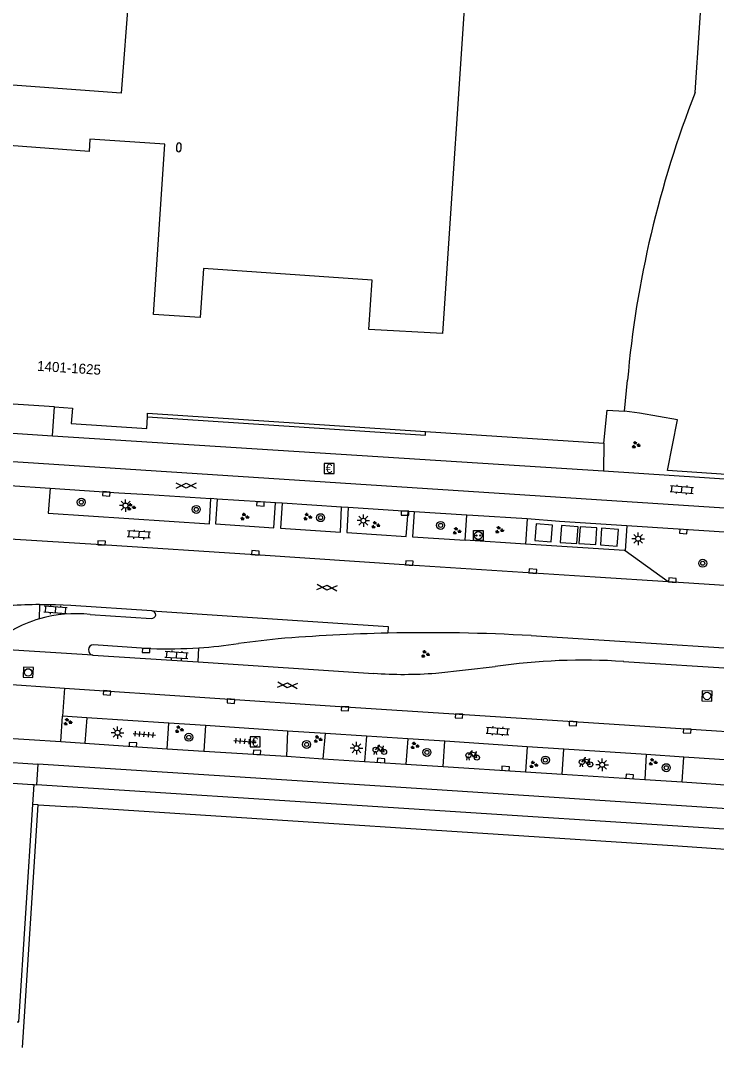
# Model space of a CAD drawing. Extents: x 132998 to 136004, y 396998 to 398512.
# Drawn here: x 133600.6 to 133670.3, y 397000 to 397102.8 of the extents above; entities that cross this region are included whole.
import ezdxf

# ---------------------------------------------------------------- set-up
doc = ezdxf.new("R2010")
doc.units = 0
for name, color, linetype in [('gg-afsc-hekwerk', 7, 'Continuous'), ('gg-anno-huisnummerreeks BGT', 7, 'Continuous'), ('gg-bbg-hoofdgebouw', 7, 'Continuous'), ('gg-bbg-onder overbouw', 7, 'Continuous'), ('gg-bbg-pand overbouw', 7, 'Continuous'), ('gg-knt-verharding', 7, 'Continuous'), ('gg-knt-verharding nz', 7, 'Continuous'), ('gg-kwrk-afval apart plaats', 7, 'Continuous'), ('gt-grn-vlakafsluiter', 7, 'Continuous'), ('gt-grn-weggrens', 7, 'Continuous'), ('gt-symb-betaalautomaat', 7, 'Continuous'), ('gt-symb-boom', 7, 'Continuous'), ('gt-symb-brandkraan', 7, 'Continuous'), ('gt-symb-fietsenrek', 7, 'Continuous'), ('gt-symb-gesloten verharding', 7, 'Continuous'), ('gt-symb-groenvak', 7, 'Continuous'), ('gt-symb-klinker verharding', 7, 'Continuous'), ('gt-symb-kolk', 7, 'Continuous'), ('gt-symb-laadpunt elektrisch vervoer', 7, 'Continuous'), ('gt-symb-lichtmast', 7, 'Continuous'), ('gt-symb-rioolschacht', 7, 'Continuous'), ('gt-symb-tegel verharding', 7, 'Continuous')]:
    doc.layers.add(name, color=color, linetype=linetype)

# ---------------------------------------------------------------- blocks, each defined once
blk = doc.blocks.new('gt0-BR')
at = {"layer": 'gt-symb-brandkraan'}
for centre, radius, start, end in [((-0.24, 0), 0.206, 107.5669, 252.4331), ((0.6, -2.66), 3, 106.892, 107.5669), ((0, -0.69), 0.938, 73.108, 106.892), ((-0.6, -2.66), 3, 72.4331, 73.108), ((0.24, 0), 0.206, 287.567, 72.4331), ((0.6, 2.66), 3, 252.4331, 253.108), ((0, 0.69), 0.938, 253.108, 286.8921), ((-0.6, 2.66), 3, 286.8921, 287.567)]:
    blk.add_arc(centre, radius, start, end, dxfattribs=at)
blk = doc.blocks.new('gt0-KOLK')
at = {"layer": 'gt-symb-kolk'}
blk.add_lwpolyline([(0, 0), (0.38, 0), (0.38, 0.4), (-0.37, 0.4), (-0.37, 0), (0, 0)], dxfattribs=at)
blk = doc.blocks.new('gt0-TEG1')
at = {"layer": 'gt-symb-tegel verharding'}
for p, q in [((-1.12, 0), (1.13, 0)), ((-0.9, -0.25), (-0.9, 0.25)), ((-0.45, -0.25), (-0.45, 0.25)), ((0, -0.25), (0, 0.25)), ((0.45, -0.25), (0.45, 0.25)), ((0.9, -0.25), (0.9, 0.25))]:
    blk.add_line(p, q, dxfattribs=at)
blk = doc.blocks.new('gt0-KL1')
at = {"layer": 'gt-symb-klinker verharding'}
for p, q in [((-1.15, 0.3), (1.15, 0.3)), ((-1, -0.3), (-1, 0.3)), ((-0.5, 0.3), (-0.5, 0.45)), ((0, -0.3), (0, 0.3)), ((0.5, 0.3), (0.5, 0.45)), ((1, -0.3), (1, 0.3)), ((-1.15, -0.3), (1.15, -0.3)), ((-0.5, -0.45), (-0.5, -0.3)), ((0.5, -0.45), (0.5, -0.3))]:
    blk.add_line(p, q, dxfattribs=at)
blk = doc.blocks.new('gt0-GRVAK')
at = {"layer": 'gt-symb-groenvak'}
for p, q in [((-0.11, 0.19), (-0.23, 0.24)), ((-0.18, 0.15), (0.09, 0.15)), ((-0.09, 0.21), (-0.16, 0.32)), ((-0.05, 0.21), (-0.05, 0.39)), ((0, 0.21), (0.06, 0.32)), ((0.02, 0.19), (0.13, 0.24)), ((0.26, -0.05), (0.2, 0.06)), ((0.31, -0.05), (0.31, 0.13)), ((0.35, -0.05), (0.41, 0.06)), ((-0.24, -0.23), (-0.36, -0.18)), ((-0.32, -0.26), (-0.05, -0.26)), ((-0.23, -0.21), (-0.29, -0.09)), ((-0.18, -0.2), (-0.18, -0.02)), ((-0.14, -0.21), (-0.07, -0.09)), ((-0.12, -0.23), (0, -0.18)), ((0.24, -0.07), (0.12, -0.02)), ((0.17, -0.11), (0.44, -0.11)), ((0.37, -0.07), (0.49, -0.02))]:
    blk.add_line(p, q, dxfattribs=at)
blk = doc.blocks.new('gt0-LMAST')
at = {"layer": 'gt-symb-lichtmast'}
for p, q in [((-0.18, 0.17), (-0.45, 0.44)), ((-0.01, 0.25), (-0.01, 0.62)), ((0.17, 0.17), (0.44, 0.44)), ((-0.26, 0), (-0.63, 0)), ((-0.18, -0.18), (-0.45, -0.45)), ((-0.01, -0.25), (-0.01, -0.63)), ((0.44, -0.45), (0.17, -0.18)), ((0.24, 0), (0.62, 0))]:
    blk.add_line(p, q, dxfattribs=at)
blk.add_circle((-0.01, 0), 0.25, dxfattribs=at)
blk = doc.blocks.new('gt0-RS')
at = {"layer": 'gt-symb-rioolschacht'}
blk.add_lwpolyline([(-0.5, -0.5), (0.5, -0.5), (0.5, 0.5), (-0.5, 0.5)], close=True, dxfattribs=at)
blk.add_circle((0, 0), 0.375, dxfattribs=at)
blk = doc.blocks.new('gt0-BOOM')
at = {"layer": 'gt-symb-boom'}
for radius in [0.4, 0.2]:
    blk.add_circle((0, 0), radius, dxfattribs=at)
blk = doc.blocks.new('gt0-FREK')
at = {"layer": 'gt-symb-fietsenrek'}
for p, q in [((0.26, 0.76), (0.29, 0.82)), ((0.54, 0.34), (0.26, 0.76)), ((0.29, 0.82), (0.77, 0.71)), ((0.77, 0.71), (0.54, 0.34)), ((0.76, 0.84), (0.87, 0.82)), ((0.77, 0.71), (0.84, 0.82)), ((0.89, 0.25), (0.77, 0.71))]:
    blk.add_line(p, q, dxfattribs=at)
for points in [[(-0.12, 0), (-0.05, 0.31), (0.05, 0.31), (0.12, 0)], [(0.04, 0.48), (0.23, 0.71), (0.26, 0.76)], [(0.29, 0.82), (0.36, 0.94), (0.45, 0.93)], [(0.54, 0.34), (0.56, 0.31), (0.89, 0.25)]]:
    blk.add_lwpolyline(points, dxfattribs=at)
for centre in [(0.04, 0.48), (0.89, 0.25)]:
    blk.add_circle(centre, 0.252, dxfattribs=at)
blk = doc.blocks.new('gt0-GESVH1')
at = {"layer": 'gt-symb-gesloten verharding'}
for p, q in [((-0.99, -0.26), (0.01, 0.24)), ((0.01, -0.26), (-0.99, 0.24)), ((0.01, 0.24), (1.01, -0.26)), ((1.01, 0.24), (0.01, -0.26))]:
    blk.add_line(p, q, dxfattribs=at)
blk = doc.blocks.new('gt0-LEV')
at = {"layer": 'gt-symb-laadpunt elektrisch vervoer'}
blk.add_lwpolyline([(-0.49, 0.5), (0.49, 0.5), (0.49, -0.5), (-0.49, -0.5)], close=True, dxfattribs=at)
for centre, radius in [((0, 0), 0.393), ((-0.19, 0), 0.0566), ((0.19, 0), 0.0566)]:
    blk.add_circle(centre, radius, dxfattribs=at)
blk = doc.blocks.new('gt0-BA')
at = {"layer": 'gt-symb-betaalautomaat'}
blk.add_lwpolyline([(-0.5, -0.51), (0.5, -0.51), (0.5, 0.49), (-0.5, 0.49)], close=True, dxfattribs=at)
blk.add_text('€', height=0.9, dxfattribs=at).set_placement((-0.36, -0.46))

msp = doc.modelspace()

# ---------------------------------------------------------------- linework, layer by layer
at = {"layer": 'gg-afsc-hekwerk'}
for p, q in [((133600.79, 397000), (133602.36, 397024.29)), ((133600.79, 397000), (133602.36, 397024.29)), ((133602.36, 397024.29), (133605.79, 397024.07)), ((133602.36, 397024.29), (133605.79, 397024.07)), ((133666.45, 397020.13), (133605.79, 397024.07)), ((133666.45, 397020.13), (133605.79, 397024.07)), ((133690.95, 397018.53), (133666.45, 397020.13)), ((133690.95, 397018.53), (133666.45, 397020.13))]:
    msp.add_line(p, q, dxfattribs=at)
msp.add_lwpolyline([(133694.45, 397060.84), (133694.48, 397060.57), (133697.15, 397060.84), (133696.74, 397055.62), (133665.4, 397057.74), (133666.4, 397062.8), (133662.61, 397063.49), (133661.11, 397063.68)], dxfattribs=at)
at = {"layer": 'gg-bbg-hoofdgebouw'}
for p, q in [((133661.11, 397063.68), (133661.39, 397066.77)), ((133641.16, 397061.65), (133659.03, 397060.48))]:
    msp.add_line(p, q, dxfattribs=at)
for points in [[(133614.52, 397145.58), (133610.67, 397095.5), (133598.44, 397096.41)], [(133668.18, 397095.57), (133669.05, 397108.54), (133645.45, 397109.99), (133642.88, 397071.45), (133635.49, 397071.85), (133635.82, 397076.8), (133618.93, 397077.94), (133618.6, 397073.05), (133613.91, 397073.35), (133615.04, 397090.41), (133607.55, 397090.9), (133607.47, 397089.68), (133598.11, 397090.36), (133597.34, 397078.54), (133592.67, 397078.86), (133592.72, 397079.67), (133565.07, 397081.52), (133564.74, 397076.63), (133560.06, 397076.94), (133561.47, 397098.82), (133552.17, 397099.42)], [(133604, 397064.1), (133605.8, 397063.98), (133605.69, 397062.45), (133613.24, 397061.93), (133613.31, 397063.1)], [(133659.03, 397060.48), (133659.36, 397063.77), (133661.11, 397063.68)]]:
    msp.add_lwpolyline(points, dxfattribs=at)
msp.add_arc((133764.66, 397057.62), 103.67, 158.529, 174.9372, dxfattribs=at)
at = {"layer": 'gg-bbg-onder overbouw'}
msp.add_line((133604, 397064.1), (133547.4, 397067.79), dxfattribs=at)
msp.add_lwpolyline([(133613.31, 397063.1), (133613.33, 397063.48), (133641.16, 397061.65)], dxfattribs=at)
at = {"layer": 'gg-bbg-pand overbouw'}
for p, q in [((133603.79, 397061.22), (133604, 397064.1)), ((133596.29, 397061.71), (133603.79, 397061.22))]:
    msp.add_line(p, q, dxfattribs=at)
msp.add_lwpolyline([(133613.31, 397063.1), (133641.15, 397061.28), (133641.16, 397061.65)], dxfattribs=at)
at = {"layer": 'gg-knt-verharding'}
for p, q in [((133696.47, 397052.34), (133548.81, 397061.91)), ((133659.03, 397060.48), (133658.98, 397057.7)), ((133658.98, 397057.7), (133697.52, 397055.19)), ((133599.54, 397056.24), (133603.57, 397055.97)), ((133620.29, 397054.88), (133619.66, 397054.93)), ((133626.8, 397054.48), (133626.13, 397054.52)), ((133632.76, 397054.08), (133626.8, 397054.48)), ((133633.42, 397054.04), (133632.76, 397054.08)), ((133639.44, 397053.65), (133633.42, 397054.04)), ((133640.04, 397053.6), (133639.44, 397053.65)), ((133645.32, 397053.27), (133640.04, 397053.6)), ((133645.13, 397050.76), (133645.32, 397053.27)), ((133645.91, 397053.24), (133645.32, 397053.27)), ((133651.35, 397052.89), (133645.91, 397053.24)), ((133651.35, 397052.89), (133651.19, 397050.38)), ((133661.32, 397052.21), (133661.15, 397049.7)), ((133692.12, 397050.22), (133661.32, 397052.21)), ((133651.19, 397050.38), (133645.13, 397050.76)), ((133665.46, 397046.6), (133661.15, 397049.7)), ((133665.46, 397046.6), (133658.15, 397047.07)), ((133602.5, 397042.9), (133602.52, 397044.31)), ((133607.57, 397043.33), (133613.69, 397042.93)), ((133690.52, 397038.72), (133651.75, 397041.21)), ((133618.38, 397038.59), (133618.47, 397039.99)), ((133626.41, 397040.89), (133622.43, 397040.43)), ((133607.84, 397039.27), (133618.38, 397038.59)), ((133618.38, 397038.59), (133635.96, 397037.44)), ((133642.2, 397037.46), (133648.13, 397038.11)), ((133661.01, 397038.63), (133690.67, 397036.75)), ((133593.19, 397036.74), (133605, 397035.97)), ((133604.64, 397030.62), (133604.82, 397033.15)), ((133607.23, 397032.99), (133604.82, 397033.15)), ((133607.23, 397032.99), (133607.04, 397030.45)), ((133615.46, 397032.45), (133607.23, 397032.99)), ((133615.29, 397029.89), (133615.46, 397032.45)), ((133619.13, 397032.21), (133615.46, 397032.45)), ((133619.13, 397032.21), (133618.97, 397029.66)), ((133627.33, 397031.67), (133619.13, 397032.21)), ((133554.05, 397031.49), (133602.32, 397028.36)), ((133592.9, 397031.37), (133604.64, 397030.62)), ((133627.33, 397031.67), (133627.23, 397029.14)), ((133631.15, 397031.42), (133627.33, 397031.67)), ((133630.93, 397028.9), (133631.15, 397031.42)), ((133635.26, 397031.15), (133631.15, 397031.42)), ((133639.38, 397030.88), (133635.26, 397031.15)), ((133639.38, 397030.88), (133639.19, 397028.36)), ((133643.09, 397030.64), (133639.38, 397030.88)), ((133604.64, 397030.62), (133607.04, 397030.45)), ((133615.29, 397029.89), (133618.97, 397029.66)), ((133618.97, 397029.66), (133627.23, 397029.14)), ((133642.94, 397028.12), (133643.09, 397030.64)), ((133651.34, 397030.09), (133643.09, 397030.64)), ((133651.34, 397030.09), (133651.19, 397027.59)), ((133655.01, 397029.85), (133651.34, 397030.09)), ((133654.86, 397027.35), (133655.01, 397029.85)), ((133663.27, 397029.31), (133655.01, 397029.85)), ((133627.23, 397029.14), (133630.93, 397028.9)), ((133630.93, 397028.9), (133635.06, 397028.63)), ((133635.06, 397028.63), (133639.19, 397028.36)), ((133663.27, 397029.31), (133663.12, 397026.82)), ((133667.03, 397029.06), (133663.27, 397029.31)), ((133666.87, 397026.57), (133667.03, 397029.06)), ((133675.43, 397028.51), (133667.03, 397029.06)), ((133602.32, 397028.36), (133602.19, 397026.29)), ((133639.19, 397028.36), (133642.94, 397028.12)), ((133642.94, 397028.12), (133651.19, 397027.59)), ((133651.19, 397027.59), (133654.86, 397027.35)), ((133654.86, 397027.35), (133663.12, 397026.82)), ((133663.12, 397026.82), (133666.87, 397026.57)), ((133666.87, 397026.57), (133675.26, 397026.02)), ((133601.84, 397024.32), (133601.97, 397026.3)), ((133601.97, 397026.3), (133602.19, 397026.29)), ((133691.05, 397020.56), (133602.19, 397026.29))]:
    msp.add_line(p, q, dxfattribs=at)
for points in [[(133603.57, 397055.97), (133603.38, 397053.46), (133619.52, 397052.4), (133619.66, 397054.93)], [(133603.57, 397055.97), (133610.44, 397055.52), (133613.45, 397055.34), (133619.66, 397054.93)], [(133620.29, 397054.88), (133620.14, 397052.39), (133625.97, 397052.01), (133626.13, 397054.52)], [(133626.13, 397054.52), (133624.65, 397054.6), (133620.29, 397054.88)], [(133626.8, 397054.48), (133626.65, 397051.96), (133632.64, 397051.56), (133632.76, 397054.08)], [(133658.15, 397047.07), (133639.53, 397048.28), (133624.11, 397049.3), (133608.7, 397050.29), (133596.26, 397051.07), (133565.43, 397053.1), (133552.27, 397053.95)], [(133633.42, 397054.04), (133633.29, 397051.52), (133639.24, 397051.12), (133639.44, 397053.65)], [(133640.04, 397053.6), (133639.86, 397051.1), (133645.13, 397050.76)], [(133661.32, 397052.21), (133654.57, 397052.65), (133651.35, 397052.89)], [(133661.15, 397049.7), (133661.1, 397049.73), (133651.19, 397050.38)], [(133688.59, 397045.11), (133678.33, 397045.76), (133665.46, 397046.6)], [(133613.75, 397043.7), (133605.64, 397044.22), (133604.09, 397044.29), (133602.52, 397044.31)], [(133613.66, 397039.91), (133613.19, 397039.92), (133607.9, 397040.3)], [(133605, 397035.97), (133633.12, 397034.1), (133644.54, 397033.37), (133655.95, 397032.61), (133685.71, 397030.67)], [(133607.04, 397030.45), (133611.84, 397030.11), (133615.29, 397029.89)], [(133685.16, 397022.97), (133641.29, 397025.85), (133602.32, 397028.36)], [(133600.25, 397002.56), (133600.43, 397002.55), (133601.84, 397024.32)]]:
    msp.add_lwpolyline(points, dxfattribs=at)
for centre, radius, start, end in [((133602.64, 396998.37), 45.95, 90.152, 97.605), ((133606.09, 397030.57), 12.84, 83.3634, 106.2181), ((133613.7, 397043.39), 0.46, 269.1351, 344.8887), ((133613.7, 397043.26), 0.444, 1.9655, 82.823), ((133606.09, 397030.57), 12.84, 106.2367, 132.5705), ((133641.37, 396861.04), 180.47, 91.2603, 94.7571), ((133641.39, 396860.82), 180.69, 86.7142, 91.2651), ((133607.93, 397039.78), 0.521, 93.788, 259.5636), ((133615.3, 397085.84), 45.95, 267.9534, 273.9528), ((133615.33, 397085.88), 46, 273.9083, 278.8769), ((133656.97, 396978.15), 60.61, 86.174, 98.3862), ((133638.97, 397079.01), 41.67, 265.8527, 274.4411)]:
    msp.add_arc(centre, radius, start, end, dxfattribs=at)
at = {"layer": 'gg-knt-verharding nz'}
for p, q in [((133607.84, 397039.27), (133597.07, 397039.92)), ((133605, 397035.97), (133604.82, 397033.15)), ((133635.26, 397031.15), (133635.06, 397028.63)), ((133601.8, 397026.31), (133601.97, 397026.3))]:
    msp.add_line(p, q, dxfattribs=at)
for points in [[(133613.75, 397043.7), (133637.42, 397042.14), (133637.4, 397041.46)], [(133593.87, 397022.76), (133594.18, 397026.8), (133601.8, 397026.31)]]:
    msp.add_lwpolyline(points, dxfattribs=at)
at = {"layer": 'gg-kwrk-afval apart plaats'}
for points in [[(133653.75, 397050.61), (133653.88, 397052.28), (133652.24, 397052.39), (133652.13, 397050.72), (133653.75, 397050.61)], [(133656.33, 397050.45), (133656.45, 397052.11), (133654.79, 397052.22), (133654.66, 397050.55), (133656.33, 397050.45)], [(133658.21, 397050.33), (133658.33, 397051.99), (133656.66, 397052.1), (133656.53, 397050.43), (133658.21, 397050.33)], [(133660.36, 397050.18), (133660.48, 397051.85), (133658.8, 397051.96), (133658.68, 397050.29), (133660.36, 397050.18)]]:
    msp.add_lwpolyline(points, dxfattribs=at)
at = {"layer": 'gt-grn-vlakafsluiter'}
msp.add_line((133602.36, 397024.29), (133601.84, 397024.32), dxfattribs=at)
at = {"layer": 'gt-grn-weggrens'}
msp.add_line((133603.79, 397061.22), (133658.98, 397057.7), dxfattribs=at)

# ---------------------------------------------------------------- block references
at = {"layer": 'gt-symb-betaalautomaat'}
for p in [(133631.52, 397057.96), (133624.1, 397030.58)]:
    msp.add_blockref('gt0-BA', p, dxfattribs=at)
at = {"layer": 'gt-symb-boom'}
for p in [(133606.69, 397054.57), (133618.2, 397053.85), (133630.66, 397053.02), (133642.68, 397052.25), (133668.93, 397048.46), (133617.46, 397031.04), (133629.26, 397030.32), (133641.31, 397029.53), (133653.17, 397028.76), (133665.28, 397028)]:
    msp.add_blockref('gt0-BOOM', p, dxfattribs=at)
at = {"layer": 'gt-symb-brandkraan', "rotation": 85.41237434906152}
msp.add_blockref('gt0-BR', (133616.46, 397090.08), dxfattribs=at)
at = {"layer": 'gt-symb-fietsenrek'}
for p in [(133636.13, 397029.32), (133645.43, 397028.76), (133656.78, 397028.08)]:
    msp.add_blockref('gt0-FREK', p, dxfattribs=at)
at = {"layer": 'gt-symb-gesloten verharding'}
msp.add_blockref('gt0-GESVH1', (133617.17, 397056.23), dxfattribs=at)
at = {"layer": 'gt-symb-gesloten verharding', "rotation": 176.27357411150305}
for p in [(133631.31, 397046.01), (133627.35, 397036.24)]:
    msp.add_blockref('gt0-GESVH1', p, dxfattribs=at)
at = {"layer": 'gt-symb-groenvak'}
for p in [(133662.22, 397060.3), (133611.67, 397054.09), (133623.03, 397053.11), (133629.33, 397053.11), (133636.14, 397052.29), (133644.28, 397051.68), (133648.54, 397051.79), (133641.12, 397039.36), (133605.31, 397032.58), (133616.47, 397031.83), (133630.36, 397030.85), (133640.07, 397030.2), (133651.97, 397028.3), (133663.92, 397028.57)]:
    msp.add_blockref('gt0-GRVAK', p, dxfattribs=at)
at = {"layer": 'gt-symb-klinker verharding'}
for p, rotation in [((133666.84, 397055.83), -4.877880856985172), ((133612.45, 397051.33), 176.273574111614), ((133604.09, 397043.78), 176.27357411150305), ((133616.22, 397039.25), 176.27357411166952), ((133648.4, 397031.68), -4.187704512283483)]:
    msp.add_blockref('gt0-KL1', p, dxfattribs=dict(at, rotation=rotation))
at = {"layer": 'gt-symb-kolk'}
for p, rotation in [((133609.22, 397055.6), 175.9266355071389), ((133624.65, 397054.6), 176.96313105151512), ((133639.12, 397053.67), 178.73969615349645), ((133667.01, 397051.84), 176.33074590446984), ((133608.7, 397050.29), -3.669254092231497), ((133624.11, 397049.3), -3.7835902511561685), ((133639.53, 397048.28), -3.7264258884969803), ((133651.9, 397047.47), -3.669254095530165), ((133665.88, 397046.57), -3.7264258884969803), ((133613.19, 397039.92), 178.39613722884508), ((133609.28, 397035.69), 176.2164097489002), ((133621.69, 397034.86), 176.15925292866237), ((133633.12, 397034.1), 176.33074590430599), ((133644.54, 397033.37), 176.15925292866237), ((133655.95, 397032.61), 176.33074590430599), ((133667.39, 397031.87), 176.2164097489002), ((133611.84, 397030.11), -4.012171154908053), ((133624.27, 397029.33), -3.5548886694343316), ((133636.7, 397028.52), -3.7264258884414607), ((133649.17, 397027.72), -3.669254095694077), ((133661.59, 397026.92), -3.7264258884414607)]:
    msp.add_blockref('gt0-KOLK', p, dxfattribs=dict(at, rotation=rotation))
at = {"layer": 'gt-symb-laadpunt elektrisch vervoer'}
msp.add_blockref('gt0-LEV', (133646.45, 397051.24), dxfattribs=at)
at = {"layer": 'gt-symb-lichtmast'}
for p in [(133611.13, 397054.23), (133634.95, 397052.72), (133662.47, 397050.91), (133610.32, 397031.5), (133634.26, 397029.95), (133658.86, 397028.29)]:
    msp.add_blockref('gt0-LMAST', p, dxfattribs=at)
at = {"layer": 'gt-symb-rioolschacht'}
for p, rotation in [((133601.37, 397037.53), -92.407413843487), ((133669.36, 397035.18), 177.9361802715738)]:
    msp.add_blockref('gt0-RS', p, dxfattribs=dict(at, rotation=rotation))
at = {"layer": 'gt-symb-tegel verharding'}
for p, rotation in [((133612.99, 397031.34), -4.877880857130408), ((133623.07, 397030.64), -4.87788086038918)]:
    msp.add_blockref('gt0-TEG1', p, dxfattribs=dict(at, rotation=rotation))

# ---------------------------------------------------------------- texts
at = {"layer": 'gg-anno-huisnummerreeks BGT'}
msp.add_text('1401-1625', height=1, rotation=356.3, dxfattribs=at).set_placement((133602.24, 397067.72))

doc.saveas('drawing.dxf')
